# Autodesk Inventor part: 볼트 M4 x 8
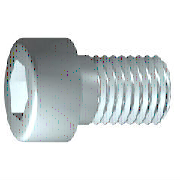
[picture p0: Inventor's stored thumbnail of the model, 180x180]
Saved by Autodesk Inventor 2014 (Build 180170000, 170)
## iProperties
IsCustomPart: 0
Created: 2012-02
Part Number: 볼트 M4 x 8
Material: 스테인리스강
Description: 6각 소켓 머리 캡 나사
Document SubType Name: Modeling
Standard: ISO 4762
Designer: mduedu
Standard Revision: Fourth edition 2004-03-01
Standards Organization: ISO
Language: ko-KR
Size Designation: M4 x 8
Categories: <MemberInstance><Categories><Category DisplayName="조임쇠" InternalName="e4da775c-781d-43d5-af7c-5136215cf5a6" Mnemonic="FSTN"><Category DisplayName="볼트" InternalN
Density: 8.08 g/cm^3
Mass: 1.89105 g
Surface Area: 2.80587 cm^2
Volume: 0.234041 cm^3
Appearance: 반광택
Author: mduedu
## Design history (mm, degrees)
sketch "스케치1"
  geometry: L1 (-1, 0)-(8, 0); L2 (8, 0)-(8, 2); L3 (8, 2)-(1.75, 2); L4 (1.75, 2)-(1.32, 2); L5 (1.32, 2)-(0, 2); L6 (0, 2)-(0, 3.5); L7 (0, 3.5)-(-4, 3.5); L8 (-4, 3.5)-(-4, 1.732); L9 (-4, 1.732)-(-2, 1.732); L10 (-2, 1.732)-(-1, 0); L11 (-6.4, 0)-(10.4, 0) reference; L12 (0, -0.7)-(0, 4.2) reference; L13 (1.75, 2)-(0, 2)
  constraints: 22 end point, 6 parallel, 2 collinear, 2 perpendicular, 1 horizontal, 1 point on line
  dimensions: "d1" = 6.25 distance from line of L3.end L2 (= GEL); "d2" = 0.42952 distance of L4.end L3.end (computed from GAL); "d3" = 4 distance between parallel lines of L8 L6 (= KOH); "d4" = 2 distance of L8.end L9.end (= INTI); "d5" = 60 deg angle of L10 L1; "d6" = 4 diameter of L3 L1 (= GD); "d7" = 4 diameter of L5 L1 (= BDM); "d8" = 3.4641 diameter of L9 L1 (= 1.1547 x SW); "d9" = 7 diameter of L7 L1 (= KOD); "d26" = 8 distance between parallel lines of L12 L2 (= NLG)
revolve "본체" sketch "스케치1" stored, may be unused: angle "d10" = 90 deg
sketch "스케치2"
  geometry: L1 (0, -4.9)-(0, 4.9) reference; L2 (-4.9, 0)-(4.9, 0) reference; L3 (1.732, 0)-(0.866, -1.5); L4 (0.866, -1.5)-(-0.866, -1.5); L5 (-0.866, -1.5)-(-1.732, 0); L6 (-1.732, 0)-(-0.866, 1.5); L7 (-0.866, 1.5)-(0.866, 1.5); L8 (0.866, 1.5)-(1.732, 0); 2 further points
  constraints: 12 end point, 1 coincident, 1 horizontal alignment, 1 point on line, 12 other
extrude "슬롯" join sketch "스케치2" stored distance "d11" = 10; taper "d12" = 0 deg
workplane "Work Plane1"
fillet "Fillet2" dims "d30" = 0.1 (= R)
body "Solid1"
fillet "모깎기1" dims "d17" = 0.4 (= RR)
feature "스레드" dims "d13" = 6.25 (= GEL), "d14" = 0
chamfer "모따기1" distance "d15" = 0.42941 (= -0.5 x SPD + 0.5 x GD); stored, may be unused: second distance "d16" = 0.42941 (= GUL), angle "d27" = 45 deg
other parameters: "GD" = 4 [user parameter; used in 2 equation terms], "NLG" = 8 [user parameter; used in 1 equation term], "GEL" = 6.25 [user parameter; used in 2 equation terms], "KOD" = 7 [user parameter; used in 1 equation term], "KOH" = 4 [user parameter; used in 1 equation term], "INTI" = 2 [user parameter; used in 1 equation term], "GAL" = 0.42941 (= 0.61345 x PTC) [user parameter; used in 1 equation term], "GUL" = 0.42941 (= 0.61345 x PTC) [user parameter; used in 1 equation term], "BDM" = 4 (= NND) [user parameter; used in 1 equation term], "SW" = 3 [user parameter; used in 2 equation terms], "RR" = 0.4 [user parameter; used in 1 equation term], "SPD" = 3.14117 (= NND - 1.2269 x PTC) [user parameter; used in 1 equation term], "d19" = 0, "d28" = 0, "d29" = 0, "R" = 0.1 [user parameter; used in 1 equation term], "TOA" = 30 deg [user parameter], "GD1" = 3.14117 (= THREADDIA - 1.2269 x PTC) [user parameter], "THREADDIA" = 4 [user parameter; used in 1 equation term], "FAWI" = 45 deg [user parameter], "TPU" = 14.28571 (computed from PTC) [user parameter], "PTC" = 0.7 [user parameter; used in 5 equation terms], "NND" = 4 [user parameter; used in 2 equation terms], "E0" = 3.465 (= 1.155 x SW) [user parameter]
